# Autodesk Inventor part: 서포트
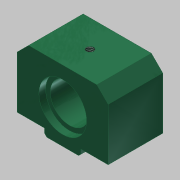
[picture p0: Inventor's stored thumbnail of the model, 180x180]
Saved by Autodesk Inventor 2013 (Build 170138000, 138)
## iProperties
Created: 2019-04
Part Number: 서포트
Material: 알루미늄 6061
Document SubType Name: Modeling
Designer: mduedu
Density: 1 g/cm^3
Author: mduedu
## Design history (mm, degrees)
sketch "스케치1"
  geometry: L1 (3, 20)-(31, 20); L2 (31, 20)-(31, -20); L3 (31, -20)-(3, -20); L4 (0, -8)-(0, 8); L5 (0, 8)-(3, 8); L6 (3, 8)-(3, 20); L7 (0, 0)-(31, 0); L8 (0, -8)-(3, -8); L9 (3, -8)-(3, -20); 1 further point
  constraints: 18 end point, 3 symmetric about line, 2 horizontal, 2 midpoint, 2 parallel, 2 perpendicular, 1 coincident
  dimensions: "d3" = 31 distance between parallel lines of L4 L2; "d5" = 16 distance of L4.start L4.end; "d6" = 40 distance between parallel lines of L3 L1; "d7" = 3 distance between parallel lines of L4 L9
extrude "돌출1" new body sketch "스케치1" distance "d8" = 24; taper "d9" = 0 deg
chamfer "모따기1" distance "d10" = 5; stored, may be unused: second distance "d11" = 2, angle "d12" = 45 deg
chamfer "모따기2" distance "d13" = 1; stored, may be unused: second distance "d14" = 2, angle "d15" = 45 deg
sketch "스케치2"
  geometry: L1 (7, 0)-(-7, 0) reference; L2 (20, 3)-(8, 3) reference; 3 further points
  constraints: 1 midpoint, 1 vertical alignment
  dimensions: "d24" = 12 distance from line of point (0, 15) L2
hole "구멍1" sketch "스케치2" at (0, 15) diameter "d17" = 17; stored, may be unused: countersink angle "d21" = 90 deg, drill point angle "d23" = 118 deg; dims "d18" = 6, "d19" = 21, "d20" = 3, "d22" = 8
sketch "스케치3"
  geometry: L1 (0, 30)-(0, 0) reference; 3 further points
  constraints: 1 horizontal alignment, 1 midpoint
  dimensions: "d25" = 12 distance from line of point (12, 15) L1
hole "구멍2" sketch "스케치3" at (12, 15) diameter "d26" = 3.242; stored, may be unused: countersink angle "d30" = 90 deg, drill point angle "d32" = 118 deg; dims "d27" = 6, "d28" = 21, "d29" = 3, "d31" = 8
sketch "스케치4"
  geometry: L1 (0, -8)-(24, -8); L2 (24, 0.5)-(24, -16.5) reference; L3 (0, -28)-(0, -23) reference; 4 further points
  constraints: 2 end point, 2 symmetric about line, 1 horizontal, 1 horizontal alignment, 1 midpoint
  dimensions: "d33" = 6 distance from line of point (6, -22) L3; "d34" = 12 distance of point (18, -22) point (6, -22); "d35" = 28 distance of point (6, 6) point (6, -22); "d36" = 14 distance from line of point (6, -22) L1 (derived)
hole "구멍3" sketch "스케치4" at (6, -22), (18, -22), (18, 6), (6, 6) diameter "d37" = 3.242; stored, may be unused: countersink angle "d41" = 90 deg, drill point angle "d43" = 118 deg; dims "d38" = 9, "d39" = 21, "d40" = 3, "d42" = 11
node "솔리드1"
